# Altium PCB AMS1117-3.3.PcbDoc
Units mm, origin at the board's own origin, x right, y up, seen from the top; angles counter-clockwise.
Board outline 17.53 x 19.61 mm, 2 copper layers (Top Layer, Bottom Layer); 1 components, 0 nets, 4 pads, 0 vias.
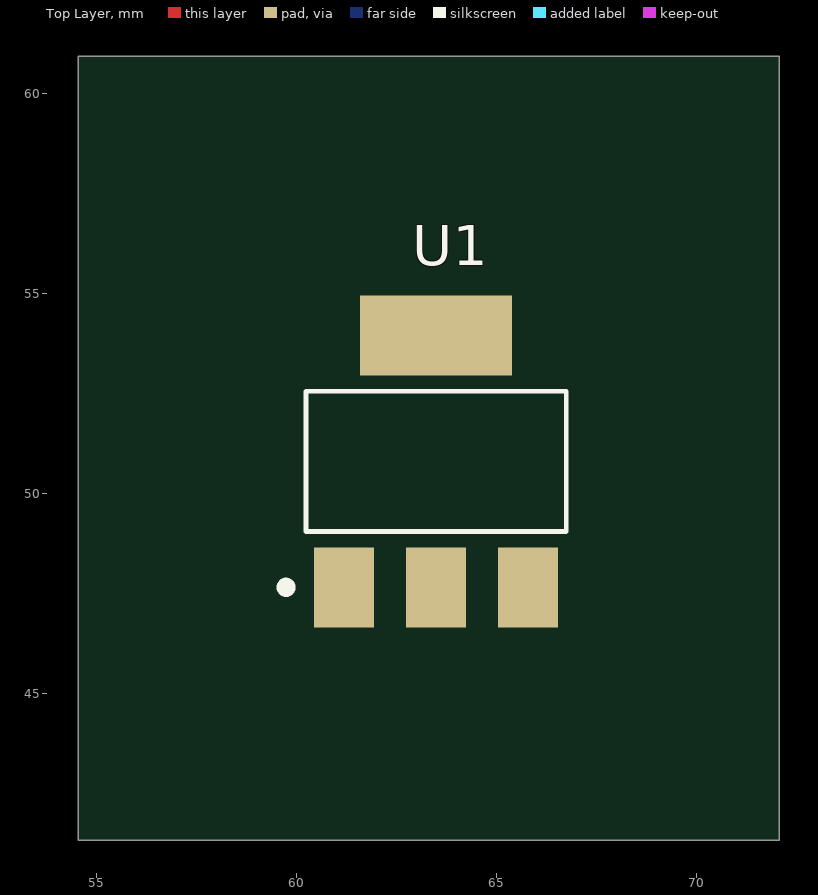
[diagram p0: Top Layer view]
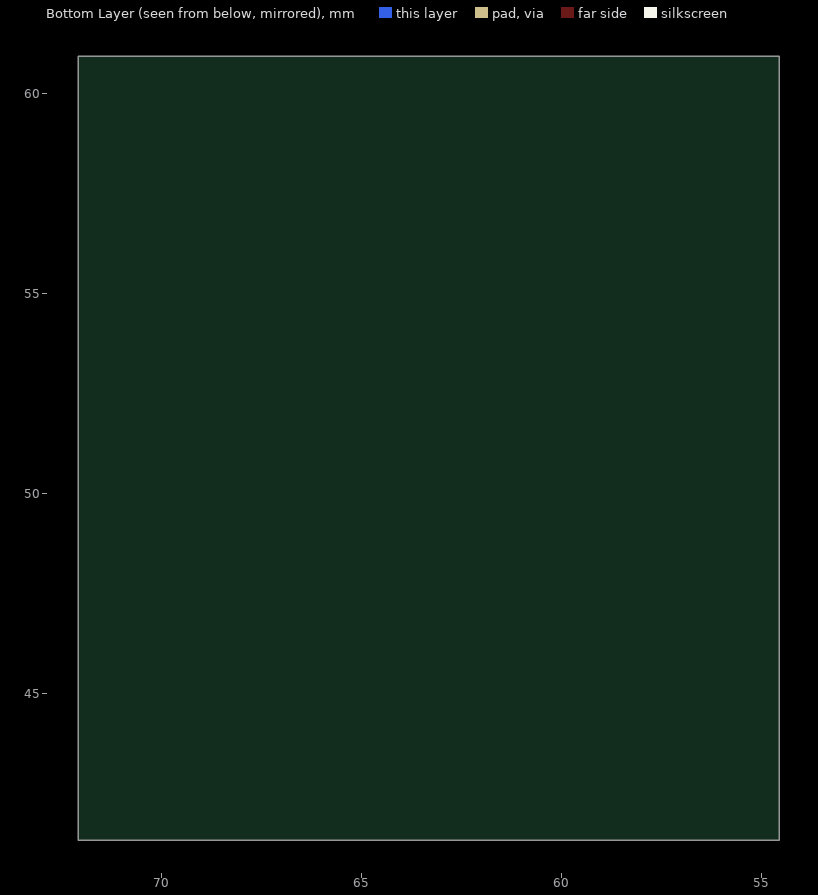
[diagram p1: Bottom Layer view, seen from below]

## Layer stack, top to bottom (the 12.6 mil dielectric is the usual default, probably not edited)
Top Layer: signal copper (thickness not stored)
Dielectric: dielectric 0.32, FR-4, Dk 4.8
Bottom Layer: signal copper (thickness not stored)

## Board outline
54.548,41.32 72.082,41.32 72.082,60.93 54.548,60.93

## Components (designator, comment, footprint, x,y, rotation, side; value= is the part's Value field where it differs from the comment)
U1 "AMS1117-3.3" SOT-223-3_TabPin2 63.5,50.8 r0 top

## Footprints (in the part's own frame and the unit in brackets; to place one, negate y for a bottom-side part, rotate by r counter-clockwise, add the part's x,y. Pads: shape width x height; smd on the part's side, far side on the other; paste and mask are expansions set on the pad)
SOT-223-3_TabPin2 [mm]
  rect 1.5x2 smd: 1(-2.3,-3.15) 2(0,-3.15) 3(2.3,-3.15)
  rect 3.8x2 smd: 2(0,3.15)
  silkscreen extent -3.87,-3.27 3.25,1.75

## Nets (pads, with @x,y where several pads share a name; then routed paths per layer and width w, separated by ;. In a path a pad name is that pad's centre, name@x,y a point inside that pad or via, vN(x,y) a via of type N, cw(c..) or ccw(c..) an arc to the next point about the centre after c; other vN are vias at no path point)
pads on no net: U1.1 U1.2 U1.3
